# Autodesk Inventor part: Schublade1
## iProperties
Created: 2008-11
Part Number: Schublade1
Project: Anlage
Material: St37k
Description: Leiste
Document SubType Name: Modellieren
Designer: GEIKON
Manufacturer: Standard
Standards Organization: Custom
Density: 7.85 g/cm^3
Author: GEIKON
Revision Number: 00
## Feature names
1. Extrusion5
2. Wandstärke1
